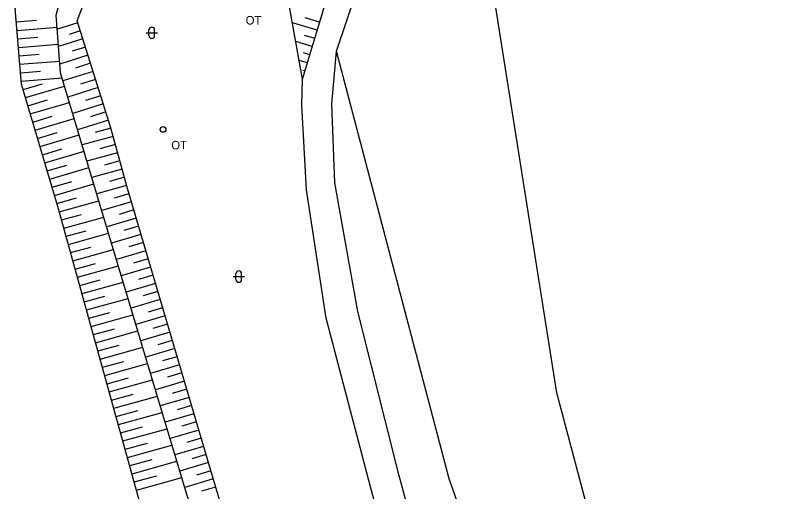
# Model space of a CAD drawing. Extents: x -762483 to -761175, y -1154655 to -1152452.
# Drawn here: x -761501.3 to -761433.6, y -1153777.6 to -1153735.6 of the extents above; entities that cross this region are included whole.
import ezdxf

# ---------------------------------------------------------------- set-up
doc = ezdxf.new("R2010")
doc.units = 0
for name, color, linetype in [('POMOC_POPIS', 7, 'Continuous'), ('ROZHRANÍ_PLOCH', 7, 'Continuous'), ('VÝŠKOPIS', 7, 'Continuous'), ('ZELEŇ', 7, 'Continuous'), ('ZN_DOPLŇKOVÉ', 7, 'Continuous'), ('ZN_KULTUR', 7, 'Continuous')]:
    doc.layers.add(name, color=color, linetype=linetype)

msp = doc.modelspace()

# ---------------------------------------------------------------- linework, layer by layer
at = {"layer": 'ROZHRANÍ_PLOCH'}
for points in [[(-761434.93, -1153874.02), (-761441.01, -1153865.81), (-761449.15, -1153852.08), (-761449.99, -1153846.27), (-761454.88, -1153824.33), (-761460.11, -1153803.11), (-761467.39, -1153776.13), (-761471.02, -1153761.75), (-761473.05, -1153750.38), (-761473.32, -1153743.45), (-761472.9, -1153738.76), (-761469.29, -1153727.99), (-761463.09, -1153717.88), (-761457.11, -1153709.26), (-761452.2, -1153699.02), (-761448.54, -1153694.34), (-761445.35, -1153692.83)], [(-761475.9, -1153741.23), (-761471.35, -1153726.1), (-761465.58, -1153716.27)], [(-761452.9, -1153853.09), (-761452.4, -1153851.26), (-761452.25, -1153849.04), (-761452.39, -1153846.91), (-761457.13, -1153824.84), (-761462.61, -1153804.18), (-761469.9, -1153777.22), (-761473.8, -1153762.33), (-761475.56, -1153751.01), (-761475.96, -1153743.54), (-761475.9, -1153741.23)]]:
    msp.add_lwpolyline(points, dxfattribs=at)
at = {"layer": 'VÝŠKOPIS'}
for p, q in [((-761475.9, -1153741.23), (-761477.46, -1153732.49)), ((-761501.164, -1153736.183), (-761499.391, -1153736.04)), ((-761474.388, -1153736.202), (-761475.661, -1153735.82)), ((-761501.103, -1153736.931), (-761497.563, -1153736.644)), ((-761495.747, -1153736.256), (-761497.55, -1153736.826)), ((-761474.604, -1153736.921), (-761476.786, -1153736.264)), ((-761495.522, -1153736.972), (-761496.508, -1153737.283)), ((-761474.82, -1153737.639), (-761475.729, -1153737.365)), ((-761501.043, -1153737.678), (-761499.276, -1153737.535)), ((-761495.296, -1153737.687), (-761497.438, -1153738.363)), ((-761475.036, -1153738.357), (-761476.491, -1153737.92)), ((-761500.982, -1153738.426), (-761497.454, -1153738.14)), ((-761495.07, -1153738.402), (-761496.226, -1153738.767)), ((-761500.922, -1153739.174), (-761499.161, -1153739.031)), ((-761494.844, -1153739.117), (-761497.327, -1153739.901)), ((-761475.252, -1153739.075), (-761475.798, -1153738.911)), ((-761500.861, -1153739.921), (-761497.346, -1153739.636)), ((-761494.618, -1153739.832), (-761495.944, -1153740.251)), ((-761475.468, -1153739.794), (-761476.195, -1153739.575)), ((-761500.8, -1153740.669), (-761499.046, -1153740.526)), ((-761494.392, -1153740.547), (-761497.057, -1153741.389)), ((-761475.684, -1153740.512), (-761475.866, -1153740.457)), ((-761500.74, -1153741.416), (-761497.137, -1153741.124)), ((-761494.166, -1153741.263), (-761495.504, -1153741.685)), ((-761500.576, -1153742.144), (-761498.857, -1153741.634)), ((-761500.363, -1153742.863), (-761496.921, -1153741.841)), ((-761493.94, -1153741.978), (-761496.625, -1153742.826)), ((-761493.714, -1153742.693), (-761495.062, -1153743.119)), ((-761500.149, -1153743.582), (-761498.427, -1153743.071)), ((-761499.936, -1153744.301), (-761496.49, -1153743.278)), ((-761493.489, -1153743.408), (-761496.194, -1153744.263)), ((-761493.263, -1153744.123), (-761494.62, -1153744.552)), ((-761499.722, -1153745.02), (-761497.998, -1153744.508)), ((-761499.508, -1153745.739), (-761496.058, -1153744.714)), ((-761493.037, -1153744.838), (-761495.762, -1153745.699)), ((-761492.816, -1153745.555), (-761494.198, -1153745.932)), ((-761499.295, -1153746.458), (-761497.569, -1153745.945)), ((-761499.081, -1153747.177), (-761495.627, -1153746.151)), ((-761492.618, -1153746.279), (-761495.363, -1153747.028)), ((-761498.868, -1153747.896), (-761497.139, -1153747.383)), ((-761498.654, -1153748.615), (-761495.195, -1153747.588)), ((-761492.421, -1153747.002), (-761493.784, -1153747.374)), ((-761492.224, -1153747.726), (-761494.932, -1153748.465)), ((-761498.441, -1153749.334), (-761496.71, -1153748.82)), ((-761492.026, -1153748.449), (-761493.371, -1153748.816)), ((-761498.227, -1153750.053), (-761494.764, -1153749.024)), ((-761491.829, -1153749.173), (-761494.5, -1153749.902)), ((-761498.014, -1153750.772), (-761496.281, -1153750.257)), ((-761491.631, -1153749.896), (-761492.958, -1153750.258)), ((-761497.8, -1153751.491), (-761494.332, -1153750.461)), ((-761491.434, -1153750.62), (-761494.068, -1153751.339)), ((-761491.227, -1153751.341), (-761492.532, -1153751.727)), ((-761497.587, -1153752.21), (-761495.852, -1153751.695)), ((-761497.378, -1153752.93), (-761493.882, -1153751.959)), ((-761491.014, -1153752.06), (-761493.621, -1153752.831)), ((-761490.801, -1153752.779), (-761492.104, -1153753.164)), ((-761497.177, -1153753.653), (-761495.422, -1153753.165)), ((-761496.976, -1153754.375), (-761493.452, -1153753.397)), ((-761490.589, -1153753.498), (-761493.191, -1153754.268)), ((-761490.376, -1153754.218), (-761491.676, -1153754.602)), ((-761496.776, -1153755.098), (-761495.006, -1153754.607)), ((-761496.575, -1153755.821), (-761493.022, -1153754.834)), ((-761490.163, -1153754.937), (-761492.761, -1153755.705)), ((-761489.951, -1153755.656), (-761491.248, -1153756.04)), ((-761496.374, -1153756.543), (-761494.59, -1153756.048)), ((-761496.174, -1153757.266), (-761492.591, -1153756.271)), ((-761489.738, -1153756.375), (-761492.33, -1153757.142)), ((-761495.973, -1153757.989), (-761494.174, -1153757.489)), ((-761495.772, -1153758.711), (-761492.161, -1153757.708)), ((-761489.525, -1153757.094), (-761490.82, -1153757.477)), ((-761489.313, -1153757.814), (-761491.9, -1153758.579)), ((-761495.572, -1153759.434), (-761493.759, -1153758.931)), ((-761489.1, -1153758.533), (-761490.392, -1153758.915)), ((-761495.371, -1153760.157), (-761491.73, -1153759.146)), ((-761488.887, -1153759.252), (-761491.47, -1153760.016)), ((-761495.17, -1153760.879), (-761493.343, -1153760.372)), ((-761488.674, -1153759.971), (-761489.965, -1153760.353)), ((-761494.97, -1153761.602), (-761491.3, -1153760.583)), ((-761488.462, -1153760.69), (-761491.039, -1153761.453)), ((-761488.249, -1153761.41), (-761489.537, -1153761.79)), ((-761494.769, -1153762.325), (-761492.927, -1153761.813)), ((-761494.568, -1153763.047), (-761490.869, -1153762.02)), ((-761488.036, -1153762.129), (-761490.609, -1153762.89)), ((-761487.824, -1153762.848), (-761489.109, -1153763.228)), ((-761494.368, -1153763.77), (-761492.511, -1153763.254)), ((-761494.167, -1153764.493), (-761490.439, -1153763.457)), ((-761487.611, -1153763.567), (-761490.179, -1153764.327)), ((-761487.398, -1153764.287), (-761488.681, -1153764.666)), ((-761493.966, -1153765.215), (-761492.095, -1153764.696)), ((-761493.765, -1153765.938), (-761490.009, -1153764.895)), ((-761487.186, -1153765.006), (-761489.748, -1153765.764)), ((-761486.973, -1153765.725), (-761488.253, -1153766.103)), ((-761493.565, -1153766.661), (-761491.679, -1153766.137)), ((-761493.364, -1153767.383), (-761489.578, -1153766.332)), ((-761486.76, -1153766.444), (-761489.318, -1153767.201)), ((-761486.548, -1153767.163), (-761487.825, -1153767.541)), ((-761493.163, -1153768.106), (-761491.263, -1153767.578)), ((-761492.963, -1153768.829), (-761489.148, -1153767.769)), ((-761486.335, -1153767.883), (-761488.888, -1153768.637)), ((-761492.762, -1153769.551), (-761490.847, -1153769.019)), ((-761492.561, -1153770.274), (-761488.717, -1153769.206)), ((-761486.122, -1153768.602), (-761487.397, -1153768.979)), ((-761485.91, -1153769.321), (-761488.457, -1153770.074)), ((-761492.361, -1153770.996), (-761490.431, -1153770.461)), ((-761485.697, -1153770.04), (-761486.97, -1153770.417)), ((-761492.16, -1153771.719), (-761488.287, -1153770.644)), ((-761485.484, -1153770.759), (-761488.027, -1153771.511)), ((-761491.959, -1153772.442), (-761490.016, -1153771.902)), ((-761485.272, -1153771.479), (-761486.542, -1153771.854)), ((-761491.759, -1153773.164), (-761487.857, -1153772.081)), ((-761485.059, -1153772.198), (-761487.597, -1153772.948)), ((-761484.846, -1153772.917), (-761486.114, -1153773.292)), ((-761491.558, -1153773.887), (-761489.6, -1153773.343)), ((-761491.357, -1153774.61), (-761487.426, -1153773.518)), ((-761484.633, -1153773.636), (-761487.166, -1153774.385)), ((-761484.421, -1153774.355), (-761485.686, -1153774.73)), ((-761491.157, -1153775.332), (-761489.184, -1153774.785)), ((-761490.956, -1153776.055), (-761486.996, -1153774.955)), ((-761484.208, -1153775.075), (-761486.736, -1153775.822)), ((-761483.995, -1153775.794), (-761485.258, -1153776.167)), ((-761490.755, -1153776.778), (-761488.768, -1153776.226)), ((-761490.555, -1153777.5), (-761486.565, -1153776.393)), ((-761483.783, -1153776.513), (-761486.306, -1153777.259)), ((-761483.57, -1153777.232), (-761484.83, -1153777.605))]:
    msp.add_line(p, q, dxfattribs=at)
for points in [[(-761466.45, -1153861.09), (-761470.91, -1153845.35), (-761474.12, -1153833.49), (-761480.65, -1153811.97), (-761483.52, -1153801.97), (-761489.28, -1153782.09), (-761497.45, -1153752.67), (-761500.72, -1153741.66), (-761501.26, -1153735), (-761498.77, -1153730.05), (-761489.93, -1153723.28)], [(-761461.34, -1153860.49), (-761466.43, -1153843.85), (-761470.44, -1153830.36), (-761476.67, -1153809.74), (-761479.95, -1153798.43), (-761484.96, -1153782.06), (-761485.27, -1153779.63), (-761486.03, -1153778.18), (-761493.99, -1153751.6), (-761497.27, -1153740.68), (-761497.64, -1153735.58), (-761496.57, -1153731.48), (-761488.74, -1153724.96)], [(-761459.81, -1153860.03), (-761464.42, -1153843.32), (-761468.06, -1153830.1), (-761474.68, -1153808.51), (-761477.99, -1153798.11), (-761483.15, -1153780.46), (-761483, -1153779.16), (-761491.36, -1153750.89), (-761492.85, -1153745.43), (-761495.8, -1153736.09), (-761494.57, -1153732.81), (-761487.82, -1153726.41)]]:
    msp.add_lwpolyline(points, dxfattribs=at)
at = {"layer": 'ZELEŇ'}
for points in [[(-761417.92, -1153885.82), (-761420.48, -1153881.04), (-761426.02, -1153861.31), (-761429.88, -1153849.29), (-761433.09, -1153841.56), (-761439.85, -1153821.78), (-761446.6, -1153794.62), (-761453.44, -1153768.91), (-761460.71, -1153722.99), (-761451.36, -1153700.45)], [(-761438.53, -1153861.96), (-761441.29, -1153851.43), (-761450.17, -1153823.28), (-761454.48, -1153800.51), (-761462.94, -1153776.49), (-761472.9, -1153738.76)]]:
    msp.add_lwpolyline(points, dxfattribs=at)
at = {"layer": 'ZN_DOPLŇKOVÉ'}
for radius in [0.25, 0.0005]:
    msp.add_circle((-761488.211, -1153745.67), radius, dxfattribs=at)
at = {"layer": 'ZN_KULTUR'}
for p, q in [((-761489.71, -1153737.14), (-761488.71, -1153737.14)), ((-761489.46, -1153737.39), (-761489.46, -1153736.89)), ((-761488.96, -1153737.39), (-761488.96, -1153736.89)), ((-761481.78, -1153758.91), (-761481.78, -1153758.41)), ((-761481.28, -1153758.91), (-761481.28, -1153758.41)), ((-761482.03, -1153758.66), (-761481.03, -1153758.66))]:
    msp.add_line(p, q, dxfattribs=at)
for centre, start, end in [((-761489.21, -1153736.89), 0, 179.99999), ((-761489.21, -1153737.39), 179.99999, 359.99999), ((-761481.53, -1153758.41), 0, 179.99999), ((-761481.53, -1153758.91), 179.99999, 359.99999)]:
    msp.add_arc(centre, 0.25, start, end, dxfattribs=at)

# ---------------------------------------------------------------- texts
at = {"layer": 'POMOC_POPIS'}
for p in [(-761480.92, -1153736.41), (-761487.49, -1153747.43)]:
    msp.add_text('OT', height=0.75, dxfattribs=at).set_placement(p)

doc.saveas('drawing.dxf')
